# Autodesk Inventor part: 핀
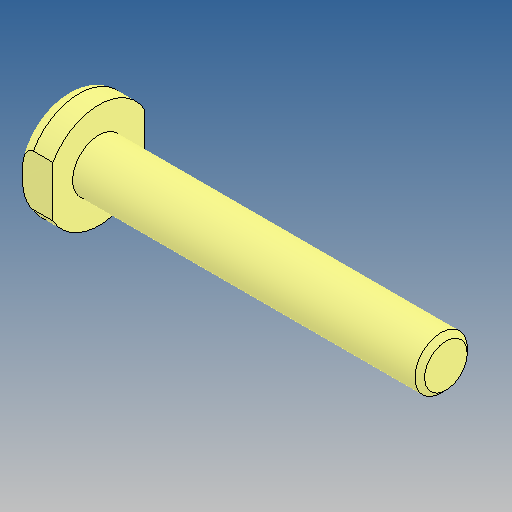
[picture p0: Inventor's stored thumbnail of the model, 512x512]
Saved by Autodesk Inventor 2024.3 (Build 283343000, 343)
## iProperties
Created: 2025-06
Part Number: 핀
Material: 강철, 연강
Document SubType Name: Modeling
Designer: user
Density: 7.85 g/cm^3
Appearance: 기본값
Author: jhkim
Sending System: Autodesk Inventor 2026
Preprocessor: ST-DEVELOPER v20.1
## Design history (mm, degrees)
node "핀1"
node "솔리드2"
node "솔리드1"
